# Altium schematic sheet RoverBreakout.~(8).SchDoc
size A
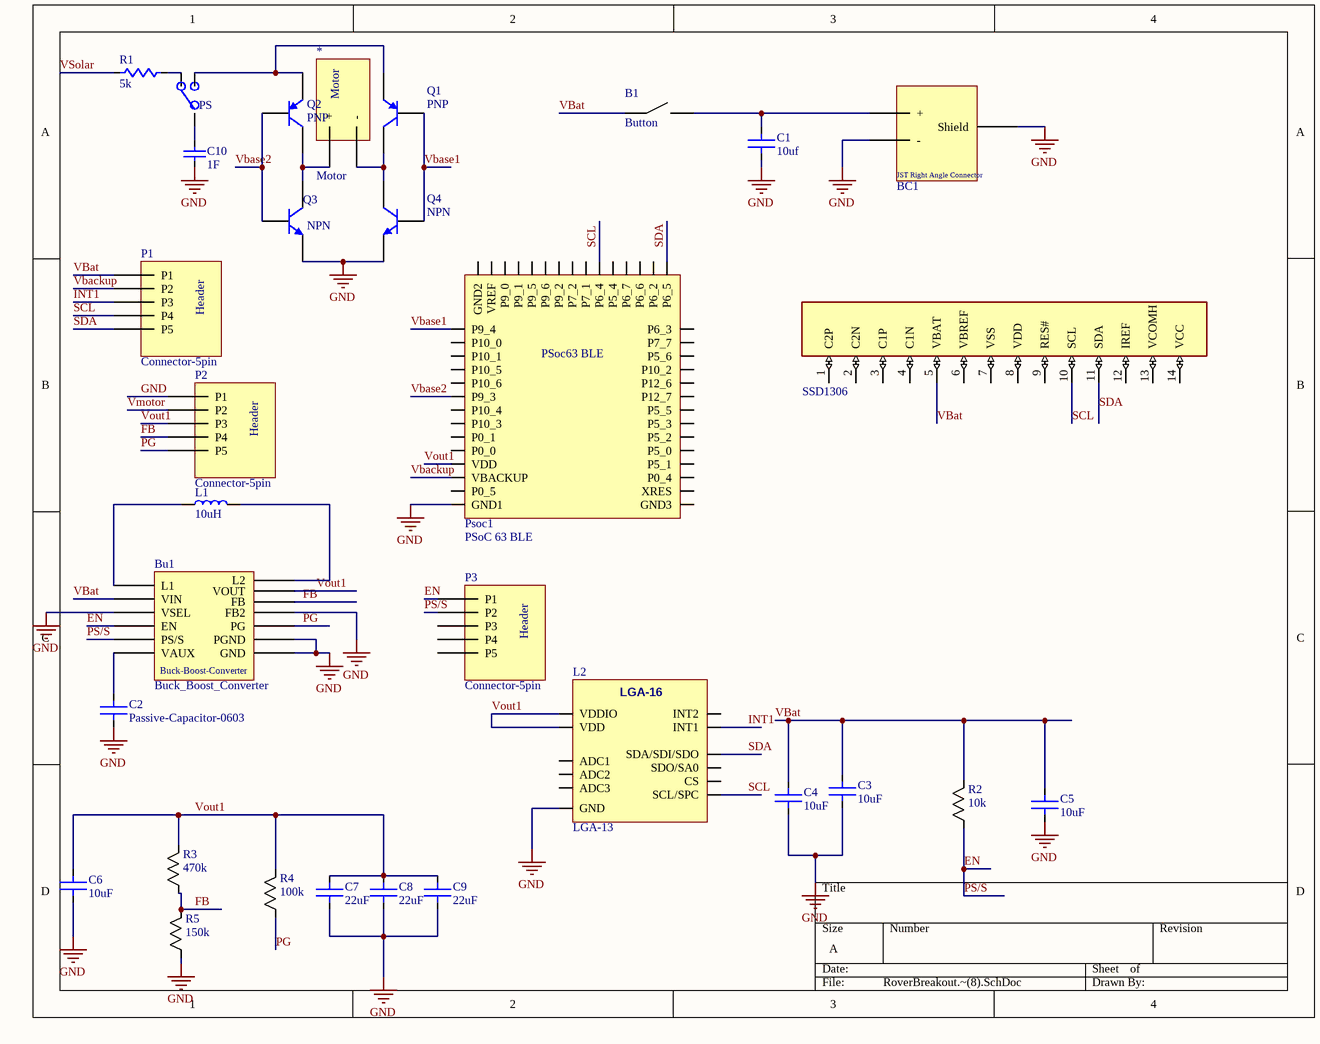
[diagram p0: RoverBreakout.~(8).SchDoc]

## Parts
*  Motor  [Motor]
?  SSD1306  [SSD1306]
B1  Button  [BUTTON]
BC1  BatteryConnector  [JST-Right-Angle-Connector-Team-7]  (value not drawn)
Bu1  Buck_Boost_Converter  [Buck_Boost_Converter]
C1  value 10uf  [PASSIVE-CAPACITOR-0603]  (hidden comment: Capacitor1)
C2  Passive-Capacitor-0603  [PASSIVE-CAPACITOR-0603]
C3  value 10uF  [PASSIVE-CAPACITOR-0603]  (hidden comment: Capacitor1)
C4  value 10uF  [PASSIVE-CAPACITOR-0603]  (hidden comment: Capacitor1)
C5  value 10uF  [PASSIVE-CAPACITOR-0603]  (hidden comment: Capacitor1)
C6  value 10uF  [PASSIVE-CAPACITOR-0603]  (hidden comment: Capacitor1)
C7  value 22uF  [PASSIVE-CAPACITOR-0603]  (hidden comment: Capacitor1)
C8  value 22uF  [PASSIVE-CAPACITOR-0603]  (hidden comment: Capacitor1)
C9  value 22uF  [PASSIVE-CAPACITOR-0603]  (hidden comment: Capacitor1)
C10  value 1F  [PASSIVE-CAPACITOR-0603]  (hidden comment: Passive-Capacitor (Generic))
L1  value 10uH  [PASSIVE-INDUCTOR-0603]  (hidden comment: Inductor)
L2  LGA-13  [LIS3DH]
P1  Connector-5pin  [CONNECTOR-HEADER-PINS]
P2  Connector-5pin  [CONNECTOR-HEADER-PINS]
P3  Connector-5pin  [CONNECTOR-HEADER-PINS]
PS  Power-Slide-Switch  [POWER-SLIDE-SWITCH]  (value not drawn)
Psoc1  PSoC 63 BLE  [PSoC-63 BLE]
Q1  PNP  [SOT-23B_N]
Q2  PNP  [SOT-23B_N]
Q3  NPN  [TO-226-AA]
Q4  NPN  [TO-226-AA]
R1  value 5k  [PASSIVE-RESISTOR-0603]  (hidden comment: Passive-Resistor (Generic))
R2  value 10k  [PASSIVE-RESISTOR-0603]  (hidden comment: Resistor)
R3  value 470k  [PASSIVE-RESISTOR-0603]  (hidden comment: Resistor)
R4  value 100k  [PASSIVE-RESISTOR-0603]  (hidden comment: Resistor)
R5  value 150k  [PASSIVE-RESISTOR-0603]  (hidden comment: Resistor)

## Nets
GND: BC1.P2(-) BC1.Shield Bu1.FB2 Bu1.GND Bu1.PGND Bu1.VSEL C1.1 C2.1 C3.1 C4.1 C5.1 C6.1 C7.1 C8.1 C9.1 C10.1 L2.GND P2.1(P1) Psoc1.1(GND1) Q3.3(E) Q4.3(E) R5.1
EN: Bu1.EN Bu1.PS/S P3.1(P1) P3.2(P2) R2.1  [also labelled PS/S]
FB: Bu1.FB P2.4(P4) R3.1 R5.2
INT1: L2.INT1 P1.3(P3)
PG: Bu1.PG P2.5(P5) R4.1
SCL: ?.10(SCL) L2.SCL/SPC P1.4(P4) Psoc1.24(P6_4)
SDA: ?.11(SDA) L2.SDA/SDI/SDO P1.5(P5) Psoc1.29(P6_5)
Vbackup: P1.2(P2) Psoc1.3(VBACKUP)
Vbase1: Psoc1.14(P9_4) Q1.2(B) Q4.2(B)
Vbase2: Psoc1.9(P9_3) Q2.2(B) Q3.2(B)
VBat: ?.5(VBAT) B1.B1 Bu1.VIN C3.2 C4.2 C5.2 P1.1(P1) R2.2
Vmotor: P2.2(P2)
Vout1: Bu1.VOUT C6.2 C7.2 C8.2 C9.2 L2.VDD L2.VDDIO P2.3(P3) Psoc1.4(VDD) R3.2 R4.2
VSolar: R1.1
Net*_1: *.1(+) Q2.1(C) Q3.1(C)
Net*_2: *.2(-) Q1.1(C) Q4.1(C)
NetB1_B3: B1.B3 BC1.P1(+) C1.2
NetBu1_L1: Bu1.L1 L1.1
NetBu1_L2: Bu1.L2 L1.2
NetBu1_VAUX: Bu1.VAUX C2.2
NetC10_2: C10.2 PS.2
NetPS_1: PS.1 R1.2
NetPS_3: PS.3 Q1.3(E) Q2.3(E)

Not connected (* = marked no-connect by the designer): ? 1(C2P) 2(C2N) 3(C1P) 4(C1N) 6(VBREF) 7(VSS) 8(VDD) 9(RES#) 12(IREF) 13(VCOMH) 14(VCC); L2 ADC1 ADC2 ADC3 CS INT2 SDO/SA0; P3 3(P3) 4(P4) 5(P5); Psoc1 2(P0_5) 5(P0_0) 6(P0_1) 7(P10_3) 8(P10_4) 10(P10_6) 11(P10_5) 12(P10_1) 13(P10_0) 15(GND2) 16(VREF) 17(P9_0) 18(P9_1) 19(P9_5) 20(P9_6) 21(P9_2) 22(P7_2) 23(P7_1) 25(P5_4) 26(P6_7) 27(P6_6) 28(P6_2) 30(P6_3) 31(P7_7) 32(P5_6) 33(P10_2) 34(P12_6) 35(P12_7) 36(P5_5) 37(P5_3) 38(P5_2) 39(P5_0) 40(P5_1) 41(P0_4) 42(XRES) 43(GND3)

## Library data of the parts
? = SSD1306: SSD1306 OLED 0.9 Display Pmodâ„¢ Platform Evaluation Expansion Board; MF: Digilent, Inc.
C10 = Passive-Capacitor (Generic): Generic Capacitor
PS = Power-Slide-Switch: DPDT, 300mA, 6V, SMD, Slide Switch; Manufacturer: Wurth Electronics; Manufacturer Part Number: 452403012014; Through Hole (y/n): N
Q1 Q2 = PNP: PNP Bipolar Transistor
Q3 Q4 = NPN: NPN Bipolar Transistor
R1 = Passive-Resistor (Generic): Generic Resistor; Through Hole (y/n): N
R2-R5 = Resistor1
